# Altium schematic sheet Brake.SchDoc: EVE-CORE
size A4; Organization: Ingenia Motion Control; Address1: Carrer Avila, 124, 2B; Address2: 08018 Barcelona Spain; Address3: www.ingeniamc.com; Address4: www.ingeniamc.com; Documentation: https://doc.ingeniamc.com/x/coAZBg
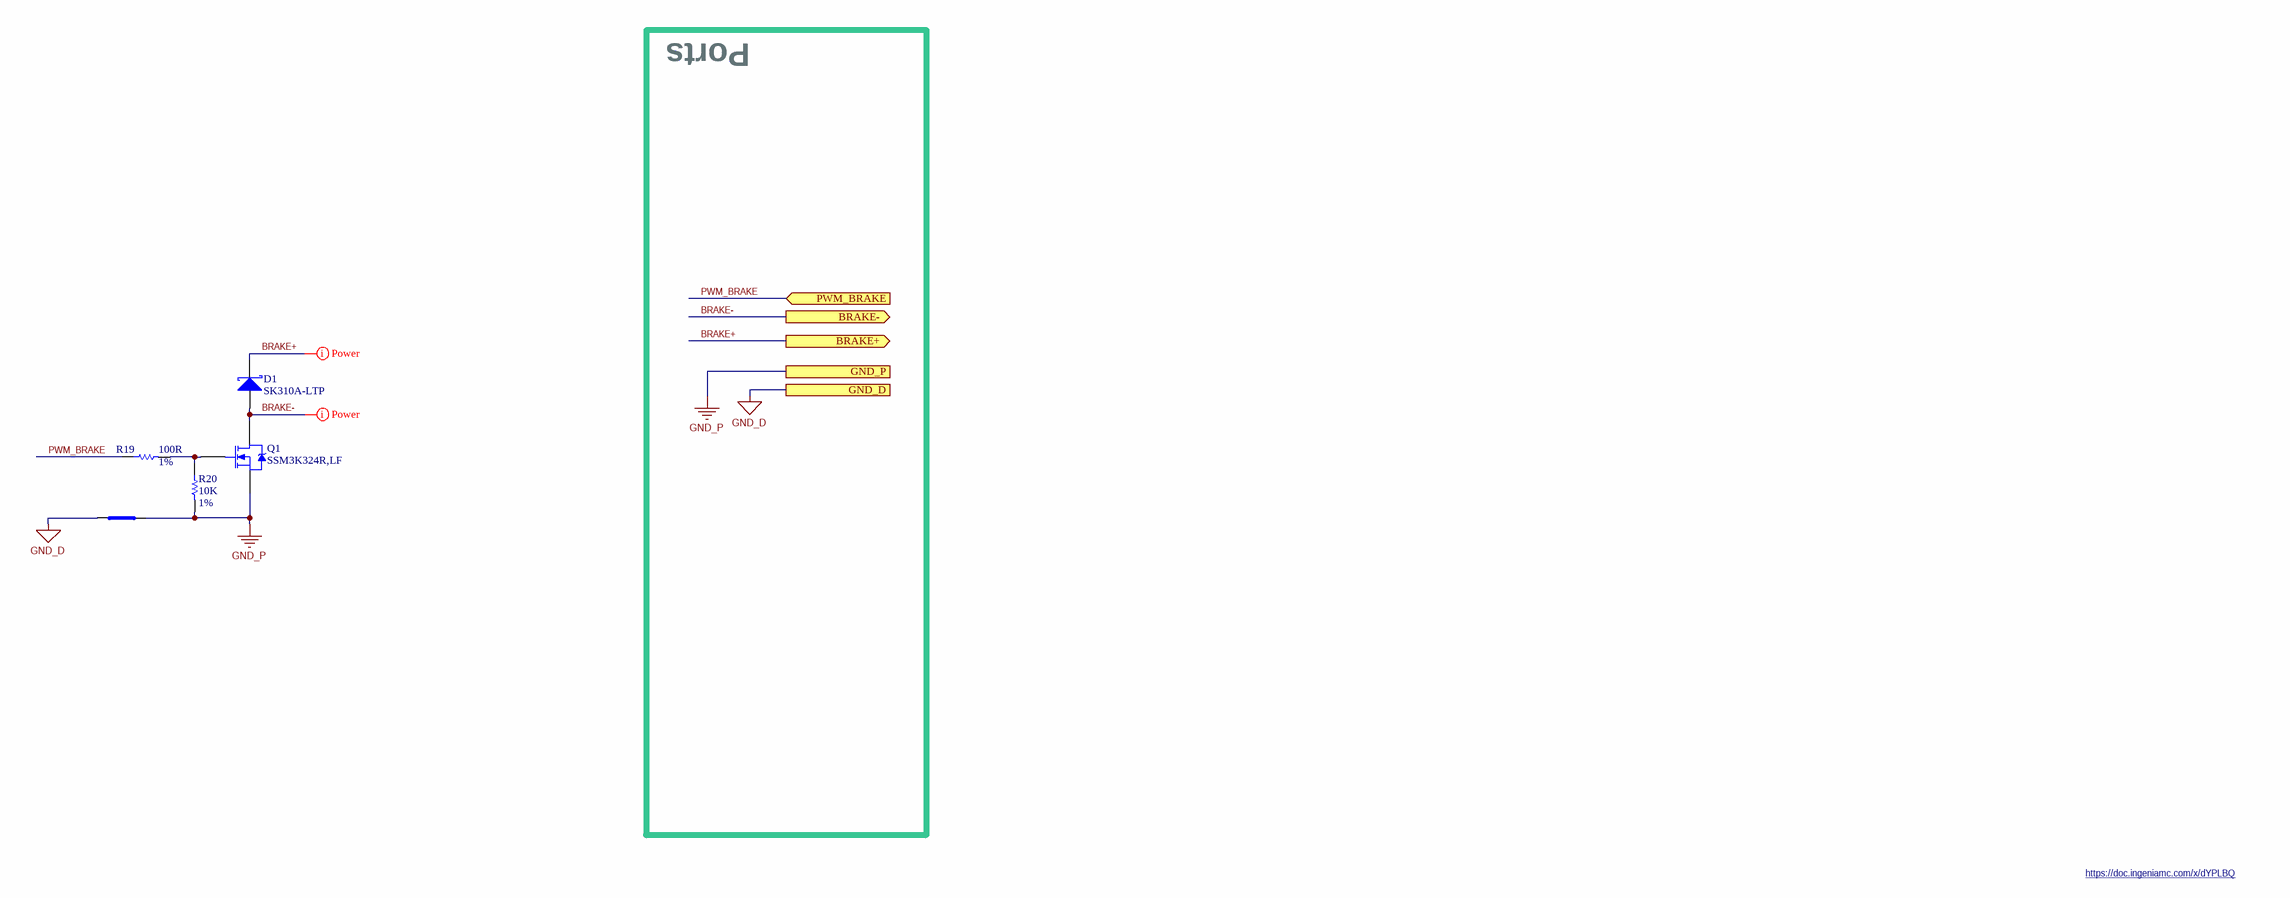
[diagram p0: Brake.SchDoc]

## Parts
D1  SK310A-LTP  [HSMA/DO-214AC]
NT1  NT2x1608  [NETTIE-SMT-1608]  (value not drawn)  (net tie, no BOM)
Q1  SSM3K324R,LF  [SOT23-3N-Wide2]
R19  value 100R  Tolerance: 1%  [R_0402]  (hidden comment: R_0402--100R--1%)
R20  value 10K  Tolerance: 1%  [R_0402]  (hidden comment: R_0402--10K--1%)

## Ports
BRAKE+ (out), BRAKE- (out), GND_D, GND_P, PWM_BRAKE (in)

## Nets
GND_D: NT1.1(Net1) ; port GND_D
GND_P: NT1.2(Net2) Q1.2(S) R20.2 ; port GND_P
BRAKE+: D1.2(K) ; port BRAKE+
BRAKE-: D1.1(A) Q1.3(D) ; port BRAKE-
PWM_BRAKE: R19.1 ; port PWM_BRAKE
NetQ1_1: Q1.1(G) R19.2 R20.1

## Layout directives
net class Power: BRAKE+, BRAKE-

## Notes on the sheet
- Ports
- https://doc.ingeniamc.com/x/dYPLBQ

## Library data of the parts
D1 = SK310A-LTP: DIODE Schottky 3 A 100 V, SMA; ManufacturerName: Micro Commercial Co; Value: 100V; IsPreferred: 0; IngeniaID: 3665; TemperatureMaxC: 125; TemperatureMinC: -50
NT1 = NT2x1608: Net-Tie, Surface Mount, 2 x 1.6mm x 0.8mm SMT Pads; ManufacturerName: Ingenia; ManufacturerPN: 8; IsPreferred: 0; IngeniaID: 465
Q1 = SSM3K324R,LF: MOSFET N-CH, 30V, 4A, 55 mOhm, SOT23-3N, LOW logic-level (<4V); ManufacturerName: Toshiba; IsPreferred: 0; IngeniaID: 4413; TemperatureMaxC: 150; TemperatureMinC: -40
R19 = R_0402[[/\]]100R[[/\]]1%: RES 100 OHM 1/16W 1% 0402 SMD; ManufacturerName: Stackpole Electronics; ManufacturerPN: RMCF0402FT100R; AlternativeManufacturer: Panasonic Electronic Components; IsPreferred: 0; IsGeneric: 1; IngeniaID: 684; TemperatureMaxC: 155; TemperatureMinC: -55; AlternativePN: ERJ-2RKF1000X
R20 = R_0402[[/\]]10K[[/\]]1%: RESISTOR 10K OHM 1/16W 1% 0402 SMD; ManufacturerName: Stackpole Electronics; ManufacturerPN: RMCF0402FT10K0; AlternativeManufacturer: Vishay Dale; IsPreferred: 0; IsGeneric: 1; IngeniaID: 685; TemperatureMaxC: 155; TemperatureMinC: -55; MTBF55h: 91649788; AlternativePN: CRCW040210K0FKED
